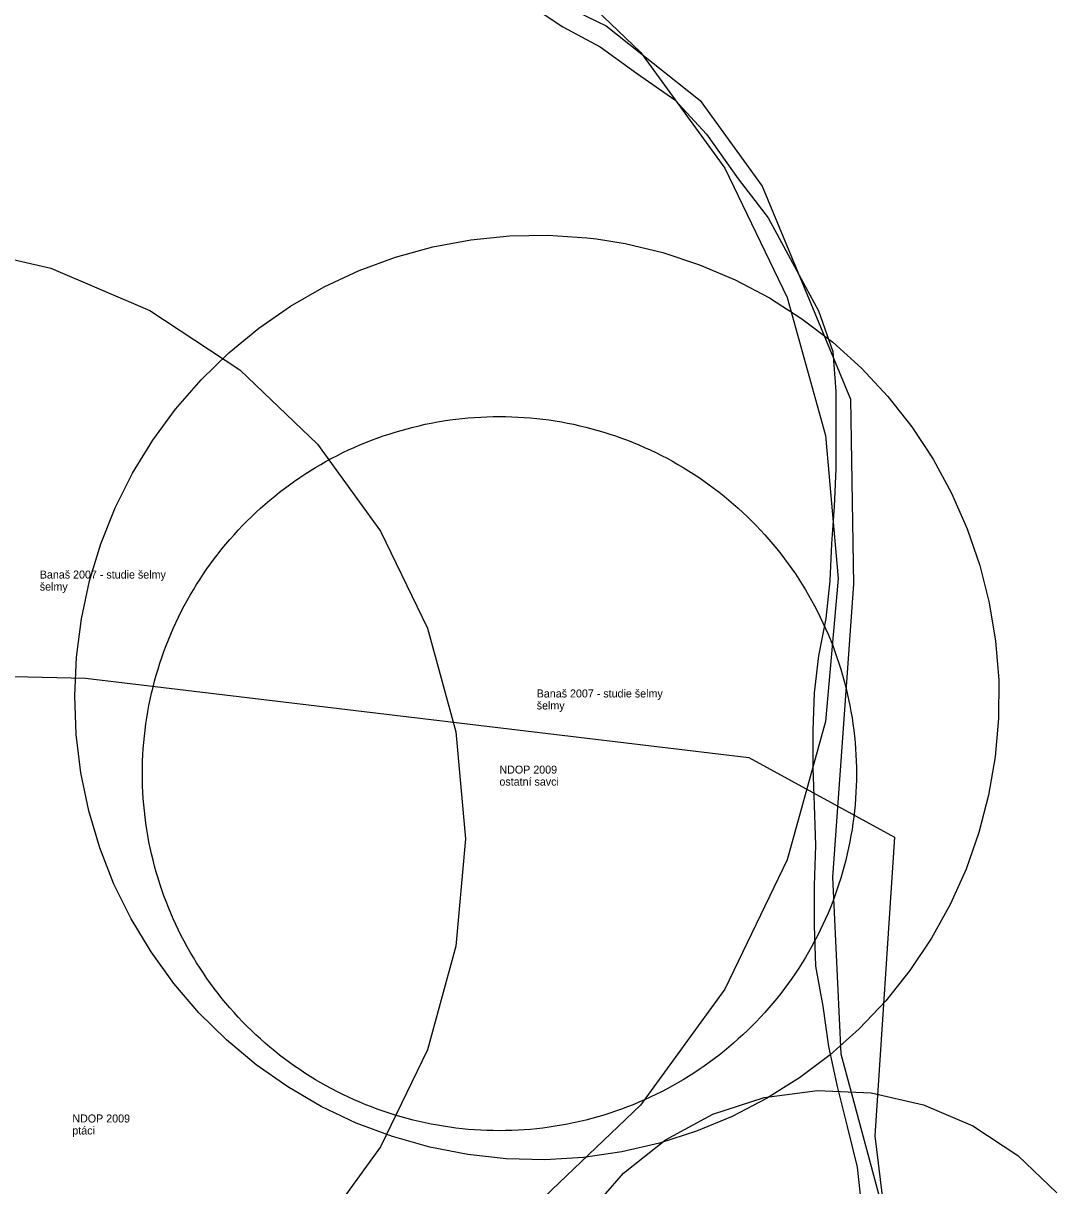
# Model space of a CAD drawing. Extents: x -477403 to -465463, y -1159182 to -1149227.
# Drawn here: x -467858.4 to -467600, y -1155094.9 to -1154804.4 of the extents above; entities that cross this region are included whole.
import ezdxf

# ---------------------------------------------------------------- set-up
doc = ezdxf.new("R2010")
doc.units = 0
for name, color, linetype in [('Vrstva 1', 7, 'Continuous'), ('Vrstva 10_stav', 7, 'Continuous'), ('Vrstva 2', 7, 'Continuous')]:
    doc.layers.add(name, color=color, linetype=linetype)

msp = doc.modelspace()

# ---------------------------------------------------------------- linework, layer by layer
at = {"layer": 'Vrstva 10_stav'}
for points in [[(-468089.099, -1154624.798), (-468066.654, -1154643.445), (-468041.101, -1154673.142), (-468008.641, -1154698.695), (-467972.038, -1154715.961), (-467931.981, -1154728.392), (-467894.688, -1154740.823), (-467854.286, -1154755.326), (-467822.517, -1154757.398), (-467796.964, -1154773.973), (-467772.101, -1154784.333), (-467741.023, -1154791.239), (-467712.707, -1154805.052), (-467689.226, -1154823.699), (-467673.687, -1154845.108), (-467651.587, -1154898.286), (-467650.896, -1154944.558), (-467656.076, -1155017.765), (-467654.004, -1155061.965), (-467644.335, -1155097.878)], [(-468089.099, -1154624.798), (-468066.654, -1154643.445), (-468041.101, -1154673.142), (-468008.641, -1154698.695), (-467972.038, -1154715.961), (-467931.982, -1154728.392), (-467894.688, -1154740.823), (-467854.286, -1154755.327), (-467822.517, -1154757.398), (-467796.964, -1154773.973), (-467772.101, -1154784.333), (-467741.023, -1154791.239), (-467712.707, -1154805.052), (-467689.226, -1154823.699), (-467673.687, -1154845.108), (-467651.587, -1154898.286), (-467650.896, -1154944.558), (-467656.076, -1155017.765), (-467654.004, -1155061.965), (-467644.335, -1155097.878)], [(-468089.099, -1154624.798), (-468066.654, -1154643.445), (-468041.101, -1154673.142), (-468008.641, -1154698.695), (-467972.038, -1154715.961), (-467931.982, -1154728.392), (-467894.688, -1154740.823), (-467854.286, -1154755.327), (-467822.517, -1154757.398), (-467796.964, -1154773.973), (-467772.101, -1154784.333), (-467741.023, -1154791.239), (-467712.707, -1154805.052), (-467689.226, -1154823.699), (-467673.687, -1154845.108), (-467651.587, -1154898.286), (-467650.896, -1154944.558), (-467656.076, -1155017.765), (-467654.004, -1155061.965), (-467644.335, -1155097.878)], [(-468089.099, -1154624.798), (-468066.654, -1154643.445), (-468041.101, -1154673.142), (-468008.641, -1154698.695), (-467972.038, -1154715.961), (-467931.982, -1154728.392), (-467894.688, -1154740.823), (-467854.286, -1154755.327), (-467822.517, -1154757.398), (-467796.964, -1154773.973), (-467772.101, -1154784.333), (-467741.023, -1154791.239), (-467712.707, -1154805.052), (-467689.226, -1154823.699), (-467673.687, -1154845.108), (-467651.587, -1154898.286), (-467650.896, -1154944.558), (-467656.076, -1155017.765), (-467654.004, -1155061.965), (-467644.335, -1155097.878)], [(-468089.099, -1154624.798), (-468066.654, -1154643.445), (-468041.101, -1154673.142), (-468008.641, -1154698.695), (-467972.038, -1154715.961), (-467931.982, -1154728.392), (-467894.688, -1154740.823), (-467854.286, -1154755.327), (-467822.517, -1154757.398), (-467796.964, -1154773.973), (-467772.101, -1154784.333), (-467741.023, -1154791.239), (-467712.707, -1154805.052), (-467689.226, -1154823.699), (-467673.687, -1154845.108), (-467651.587, -1154898.286), (-467650.896, -1154944.558), (-467656.076, -1155017.765), (-467654.004, -1155061.965), (-467644.335, -1155097.878)], [(-467729.982, -1154786.79), (-467704.066, -1154811.569), (-467682.99, -1154840.577), (-467667.433, -1154872.882), (-467657.894, -1154907.445), (-467654.68, -1154943.157), (-467657.894, -1154978.868), (-467667.433, -1155013.432), (-467682.99, -1155045.737), (-467704.066, -1155074.745), (-467729.982, -1155099.523)], [(-467732.844, -1154799.125), (-467723.5, -1154805.25), (-467714.188, -1154810.25), (-467704.844, -1154817), (-467695.5, -1154823.5), (-467687.625, -1154832.125), (-467679.719, -1154843.25), (-467672.188, -1154853), (-467665, -1154866.25), (-467659.625, -1154876.25), (-467656.031, -1154886.375), (-467655.312, -1154896.375), (-467655.312, -1154906.5), (-467655.312, -1154915.75), (-467655.656, -1154925.125), (-467656.375, -1154934.5), (-467656.75, -1154943.75), (-467657.812, -1154953.125), (-467659.625, -1154962.5), (-467660.688, -1154971.75), (-467661.062, -1154981.125), (-467661.062, -1154990.5), (-467660.688, -1154999.75), (-467660.344, -1155009.875), (-467660.688, -1155019.875), (-467660.688, -1155029.875), (-467660.344, -1155040), (-467658.531, -1155050), (-467657.094, -1155060.125), (-467654.938, -1155070.125), (-467652.438, -1155080.125), (-467649.906, -1155090.25), (-467648.844, -1155100.25)], [(-467877.695, -1154859.598), (-467851.477, -1154865.582), (-467826.75, -1154876.151), (-467804.307, -1154890.965), (-467784.869, -1154909.549), (-467769.063, -1154931.305), (-467757.395, -1154955.534), (-467750.241, -1154981.456), (-467747.83, -1155008.24), (-467750.241, -1155035.024), (-467757.395, -1155060.946), (-467769.063, -1155085.175), (-467784.869, -1155106.931)], [(-467823.241, -1154961.383), (-467822.695, -1154959.924), (-467822.124, -1154958.475), (-467821.528, -1154957.036), (-467820.907, -1154955.608), (-467820.261, -1154954.19), (-467819.591, -1154952.784), (-467818.896, -1154951.39), (-467818.176, -1154950.009), (-467817.433, -1154948.64), (-467816.666, -1154947.284), (-467815.876, -1154945.942), (-467815.062, -1154944.614), (-467814.225, -1154943.301), (-467813.365, -1154942.002), (-467812.483, -1154940.718), (-467811.579, -1154939.45), (-467810.652, -1154938.198), (-467809.704, -1154936.962), (-467808.734, -1154935.743), (-467807.743, -1154934.541), (-467806.732, -1154933.357), (-467805.7, -1154932.19), (-467804.647, -1154931.042), (-467803.575, -1154929.912), (-467802.484, -1154928.801), (-467801.373, -1154927.709), (-467800.243, -1154926.637), (-467799.094, -1154925.585), (-467797.928, -1154924.553), (-467796.743, -1154923.541), (-467795.542, -1154922.551), (-467794.323, -1154921.581), (-467793.087, -1154920.633), (-467791.835, -1154919.706), (-467790.567, -1154918.802), (-467789.283, -1154917.919), (-467787.984, -1154917.06), (-467786.67, -1154916.223), (-467785.342, -1154915.409), (-467784, -1154914.618), (-467782.645, -1154913.851), (-467781.276, -1154913.108), (-467779.894, -1154912.389), (-467778.5, -1154911.694), (-467777.094, -1154911.023), (-467775.677, -1154910.378), (-467774.249, -1154909.756), (-467772.81, -1154909.16), (-467771.36, -1154908.59), (-467769.901, -1154908.044), (-467768.433, -1154907.524), (-467766.956, -1154907.03), (-467765.471, -1154906.562), (-467763.977, -1154906.119), (-467762.476, -1154905.703), (-467760.968, -1154905.313), (-467759.454, -1154904.949), (-467757.933, -1154904.612), (-467756.407, -1154904.302), (-467754.875, -1154904.018), (-467753.339, -1154903.761), (-467751.798, -1154903.53), (-467750.254, -1154903.327), (-467748.707, -1154903.151), (-467747.156, -1154903.002), (-467745.603, -1154902.879), (-467744.049, -1154902.784), (-467742.493, -1154902.716), (-467740.935, -1154902.676), (-467739.378, -1154902.662), (-467737.82, -1154902.676), (-467736.263, -1154902.716), (-467734.707, -1154902.784), (-467733.153, -1154902.879), (-467731.6, -1154903.002), (-467730.049, -1154903.151), (-467728.502, -1154903.327), (-467726.957, -1154903.53), (-467725.417, -1154903.761), (-467723.881, -1154904.018), (-467722.349, -1154904.302), (-467720.823, -1154904.612), (-467719.302, -1154904.949), (-467717.788, -1154905.313), (-467716.28, -1154905.703), (-467714.779, -1154906.119), (-467713.285, -1154906.562), (-467711.8, -1154907.03), (-467710.323, -1154907.524), (-467708.854, -1154908.044), (-467707.395, -1154908.59), (-467705.946, -1154909.16), (-467704.507, -1154909.756), (-467703.079, -1154910.378), (-467701.661, -1154911.023), (-467700.256, -1154911.694), (-467698.862, -1154912.389), (-467697.48, -1154913.108), (-467696.111, -1154913.851), (-467694.756, -1154914.618)], [(-467694.756, -1154914.618), (-467693.413, -1154915.409), (-467692.085, -1154916.223), (-467690.772, -1154917.06), (-467689.473, -1154917.919), (-467688.189, -1154918.802), (-467686.921, -1154919.706), (-467685.669, -1154920.633), (-467684.433, -1154921.581), (-467683.214, -1154922.551), (-467682.013, -1154923.541), (-467680.828, -1154924.553), (-467679.662, -1154925.585), (-467678.513, -1154926.637), (-467677.383, -1154927.709), (-467676.272, -1154928.801), (-467675.181, -1154929.912), (-467674.108, -1154931.042), (-467673.056, -1154932.19), (-467672.024, -1154933.357), (-467671.012, -1154934.541), (-467670.022, -1154935.743), (-467669.052, -1154936.962), (-467668.104, -1154938.198), (-467667.177, -1154939.45), (-467666.273, -1154940.718), (-467665.391, -1154942.002), (-467664.531, -1154943.301), (-467663.694, -1154944.614), (-467662.88, -1154945.942), (-467662.09, -1154947.284), (-467661.323, -1154948.64), (-467660.579, -1154950.009), (-467659.86, -1154951.39), (-467659.165, -1154952.784), (-467658.495, -1154954.19), (-467657.849, -1154955.608), (-467657.228, -1154957.036), (-467656.632, -1154958.475), (-467656.061, -1154959.924), (-467655.515, -1154961.383), (-467654.995, -1154962.851), (-467654.501, -1154964.329), (-467654.033, -1154965.814), (-467653.59, -1154967.308), (-467653.174, -1154968.808), (-467652.784, -1154970.316), (-467652.421, -1154971.831), (-467652.083, -1154973.352), (-467651.773, -1154974.878), (-467651.489, -1154976.41), (-467651.232, -1154977.946), (-467651.002, -1154979.486), (-467650.798, -1154981.031), (-467650.622, -1154982.578), (-467650.473, -1154984.129), (-467650.351, -1154985.681), (-467650.255, -1154987.236), (-467650.188, -1154988.792), (-467650.147, -1154990.349), (-467650.133, -1154991.907)], [(-467754.875, -1155079.796), (-467756.407, -1155079.512), (-467757.933, -1155079.201), (-467759.454, -1155078.864), (-467760.968, -1155078.501), (-467762.476, -1155078.111), (-467763.977, -1155077.694), (-467765.471, -1155077.252), (-467766.956, -1155076.784), (-467768.433, -1155076.289), (-467769.901, -1155075.769), (-467771.36, -1155075.224), (-467772.81, -1155074.653), (-467774.249, -1155074.057), (-467775.677, -1155073.436), (-467777.094, -1155072.79), (-467778.5, -1155072.119), (-467779.894, -1155071.424), (-467781.276, -1155070.705), (-467782.645, -1155069.962), (-467784, -1155069.195), (-467785.342, -1155068.404), (-467786.67, -1155067.591), (-467787.984, -1155066.754), (-467789.283, -1155065.894), (-467790.567, -1155065.012), (-467791.835, -1155064.107), (-467793.087, -1155063.181), (-467794.323, -1155062.233), (-467795.542, -1155061.263), (-467796.743, -1155060.272), (-467797.928, -1155059.261), (-467799.094, -1155058.229), (-467800.243, -1155057.176), (-467801.373, -1155056.104), (-467802.484, -1155055.012), (-467803.575, -1155053.901), (-467804.647, -1155052.772), (-467805.7, -1155051.623), (-467806.732, -1155050.457), (-467807.743, -1155049.272), (-467808.734, -1155048.07), (-467809.704, -1155046.851), (-467810.652, -1155045.616), (-467811.579, -1155044.363), (-467812.483, -1155043.095), (-467813.365, -1155041.812), (-467814.225, -1155040.513), (-467815.062, -1155039.199), (-467815.876, -1155037.871), (-467816.666, -1155036.529), (-467817.433, -1155035.173), (-467818.176, -1155033.805), (-467818.896, -1155032.423), (-467819.591, -1155031.029), (-467820.261, -1155029.623), (-467820.907, -1155028.206), (-467821.528, -1155026.777), (-467822.124, -1155025.338), (-467822.695, -1155023.889), (-467823.241, -1155022.43), (-467823.761, -1155020.962), (-467824.255, -1155019.485), (-467824.723, -1155017.999), (-467825.166, -1155016.506), (-467825.582, -1155015.005), (-467825.972, -1155013.497), (-467826.335, -1155011.982), (-467826.673, -1155010.462), (-467826.983, -1155008.935), (-467827.267, -1155007.404), (-467827.524, -1155005.868), (-467827.754, -1155004.327), (-467827.958, -1155002.783), (-467828.134, -1155001.235), (-467828.283, -1154999.685), (-467828.405, -1154998.132), (-467828.5, -1154996.577), (-467828.568, -1154995.021), (-467828.609, -1154993.464), (-467828.623, -1154991.907), (-467828.609, -1154990.349), (-467828.568, -1154988.792), (-467828.5, -1154987.236), (-467828.405, -1154985.681), (-467828.283, -1154984.129), (-467828.134, -1154982.578), (-467827.958, -1154981.031), (-467827.754, -1154979.486), (-467827.524, -1154977.946), (-467827.267, -1154976.41), (-467826.983, -1154974.878), (-467826.673, -1154973.352), (-467826.335, -1154971.831), (-467825.972, -1154970.316), (-467825.582, -1154968.808), (-467825.166, -1154967.308), (-467824.723, -1154965.814), (-467824.255, -1154964.329), (-467823.761, -1154962.851), (-467823.241, -1154961.383)], [(-467650.133, -1154991.907), (-467650.147, -1154993.464), (-467650.188, -1154995.021), (-467650.255, -1154996.577), (-467650.351, -1154998.132), (-467650.473, -1154999.685), (-467650.622, -1155001.235), (-467650.798, -1155002.783), (-467651.002, -1155004.327), (-467651.232, -1155005.868), (-467651.489, -1155007.404), (-467651.773, -1155008.935), (-467652.083, -1155010.462), (-467652.421, -1155011.982), (-467652.784, -1155013.497), (-467653.174, -1155015.005), (-467653.59, -1155016.506), (-467654.033, -1155017.999), (-467654.501, -1155019.485), (-467654.995, -1155020.962), (-467655.515, -1155022.43), (-467656.061, -1155023.889), (-467656.632, -1155025.338), (-467657.228, -1155026.777), (-467657.849, -1155028.206), (-467658.495, -1155029.623), (-467659.165, -1155031.029), (-467659.86, -1155032.423), (-467660.579, -1155033.805), (-467661.323, -1155035.173), (-467662.09, -1155036.529), (-467662.88, -1155037.871), (-467663.694, -1155039.199), (-467664.531, -1155040.513), (-467665.391, -1155041.812), (-467666.273, -1155043.095), (-467667.177, -1155044.363), (-467668.104, -1155045.616), (-467669.052, -1155046.851), (-467670.022, -1155048.07), (-467671.012, -1155049.272), (-467672.024, -1155050.457), (-467673.056, -1155051.623), (-467674.108, -1155052.772), (-467675.181, -1155053.901), (-467676.272, -1155055.012), (-467677.383, -1155056.104), (-467678.513, -1155057.176), (-467679.662, -1155058.229), (-467680.828, -1155059.261), (-467682.013, -1155060.272), (-467683.214, -1155061.263), (-467684.433, -1155062.233), (-467685.669, -1155063.181), (-467686.921, -1155064.107), (-467688.189, -1155065.012), (-467689.473, -1155065.894), (-467690.772, -1155066.754), (-467692.085, -1155067.591), (-467693.413, -1155068.404), (-467694.756, -1155069.195), (-467696.111, -1155069.962), (-467697.48, -1155070.705), (-467698.862, -1155071.424), (-467700.256, -1155072.119), (-467701.661, -1155072.79), (-467703.079, -1155073.436), (-467704.507, -1155074.057), (-467705.946, -1155074.653), (-467707.395, -1155075.224), (-467708.854, -1155075.769), (-467710.323, -1155076.289), (-467711.8, -1155076.784), (-467713.285, -1155077.252), (-467714.779, -1155077.694), (-467716.28, -1155078.111), (-467717.788, -1155078.501), (-467719.302, -1155078.864), (-467720.823, -1155079.201), (-467722.349, -1155079.512), (-467723.881, -1155079.796), (-467725.417, -1155080.053), (-467726.957, -1155080.283), (-467728.502, -1155080.486), (-467730.049, -1155080.663), (-467731.6, -1155080.812), (-467733.153, -1155080.934), (-467734.707, -1155081.029), (-467736.263, -1155081.097), (-467737.82, -1155081.138), (-467739.378, -1155081.152), (-467740.935, -1155081.138), (-467742.493, -1155081.097), (-467744.049, -1155081.029), (-467745.603, -1155080.934), (-467747.156, -1155080.812), (-467748.707, -1155080.663), (-467750.254, -1155080.486), (-467751.798, -1155080.283), (-467753.339, -1155080.053), (-467754.875, -1155079.796)], [(-467717.206, -1155101.906), (-467708.36, -1155091.78), (-467697.847, -1155083.397), (-467686.007, -1155077.025), (-467673.219, -1155072.87), (-467659.895, -1155071.066), (-467646.463, -1155071.669), (-467633.354, -1155074.661), (-467620.99, -1155079.945), (-467609.768, -1155087.353), (-467600.05, -1155096.645)]]:
    msp.add_lwpolyline(points, dxfattribs=at)
for points in [[(-467715.136, -1154858.287), (-467707.971, -1154859.447), (-467698.557, -1154861.689), (-467689.364, -1154864.711), (-467680.457, -1154868.492), (-467671.897, -1154873.005), (-467663.744, -1154878.218), (-467656.057, -1154884.095), (-467648.888, -1154890.595), (-467642.288, -1154897.672), (-467636.303, -1154905.276), (-467630.976, -1154913.355), (-467626.344, -1154921.85), (-467622.438, -1154930.704), (-467619.287, -1154939.854), (-467616.913, -1154949.235), (-467615.332, -1154958.781), (-467614.556, -1154968.427), (-467614.589, -1154978.104), (-467615.432, -1154987.744), (-467617.079, -1154997.279), (-467619.518, -1155006.644), (-467622.732, -1155015.771), (-467626.698, -1155024.598), (-467631.389, -1155033.061), (-467636.772, -1155041.103), (-467642.809, -1155048.666), (-467649.457, -1155055.697), (-467656.671, -1155062.147), (-467664.398, -1155067.971), (-467672.587, -1155073.128), (-467681.178, -1155077.581), (-467690.111, -1155081.301), (-467699.325, -1155084.259), (-467708.753, -1155086.436), (-467718.331, -1155087.817), (-467727.991, -1155088.391), (-467737.665, -1155088.155), (-467747.285, -1155087.111), (-467756.784, -1155085.265), (-467766.095, -1155082.63), (-467775.153, -1155079.226), (-467783.895, -1155075.076), (-467792.259, -1155070.208), (-467800.186, -1155064.658), (-467807.62, -1155058.464), (-467814.511, -1155051.67), (-467820.808, -1155044.323), (-467826.469, -1155036.475), (-467831.454, -1155028.18), (-467835.726, -1155019.498), (-467839.258, -1155010.489), (-467842.022, -1155001.215), (-467844.002, -1154991.743), (-467845.181, -1154982.138), (-467845.553, -1154972.469), (-467845.115, -1154962.802), (-467843.869, -1154953.206), (-467841.824, -1154943.747), (-467838.995, -1154934.493), (-467835.402, -1154925.508), (-467831.07, -1154916.856), (-467826.028, -1154908.596), (-467820.314, -1154900.787), (-467813.965, -1154893.483), (-467807.028, -1154886.737), (-467799.551, -1154880.594), (-467791.586, -1154875.099), (-467783.189, -1154870.29), (-467774.419, -1154866.2), (-467765.337, -1154862.858), (-467756.008, -1154860.288), (-467746.497, -1154858.507), (-467736.869, -1154857.529), (-467727.194, -1154857.36), (-467717.539, -1154858.001)], [(-468058.329, -1154963.054), (-467987.047, -1154964.711), (-467842.825, -1154968.027), (-467677.052, -1154987.919), (-467640.582, -1155007.812), (-467645.555, -1155082.41), (-467635.609, -1155163.639), (-467633.951, -1155195.135), (-467988.705, -1155158.665), (-468058.329, -1154966.369)]]:
    msp.add_lwpolyline(points, close=True, dxfattribs=at)

# ---------------------------------------------------------------- texts
at = {"layer": 'Vrstva 1'}
for s, p in [('šelmy', (-467854.278, -1154946.157)), ('šelmy', (-467854.278, -1154946.157)), ('šelmy', (-467730.055, -1154975.875)), ('šelmy', (-467730.055, -1154975.875)), ('ostatní savci', (-467739.378, -1154994.907)), ('ostatní savci', (-467739.378, -1154994.907)), ('ptáci', (-467846.14, -1155082.094)), ('ptáci', (-467846.14, -1155082.094))]:
    msp.add_text(s, height=2, dxfattribs=at).set_placement(p)
at = {"layer": 'Vrstva 2'}
for s, p in [('Banaš 2007 - studie šelmy', (-467854.278, -1154943.157)), ('Banaš 2007 - studie šelmy', (-467854.278, -1154943.157)), ('Banaš 2007 - studie šelmy', (-467730.055, -1154972.875)), ('Banaš 2007 - studie šelmy', (-467730.055, -1154972.875)), ('NDOP 2009', (-467739.378, -1154991.907)), ('NDOP 2009', (-467739.378, -1154991.907)), ('NDOP 2009', (-467846.14, -1155079.094)), ('NDOP 2009', (-467846.14, -1155079.094))]:
    msp.add_text(s, height=2, dxfattribs=at).set_placement(p)

doc.saveas('drawing.dxf')
